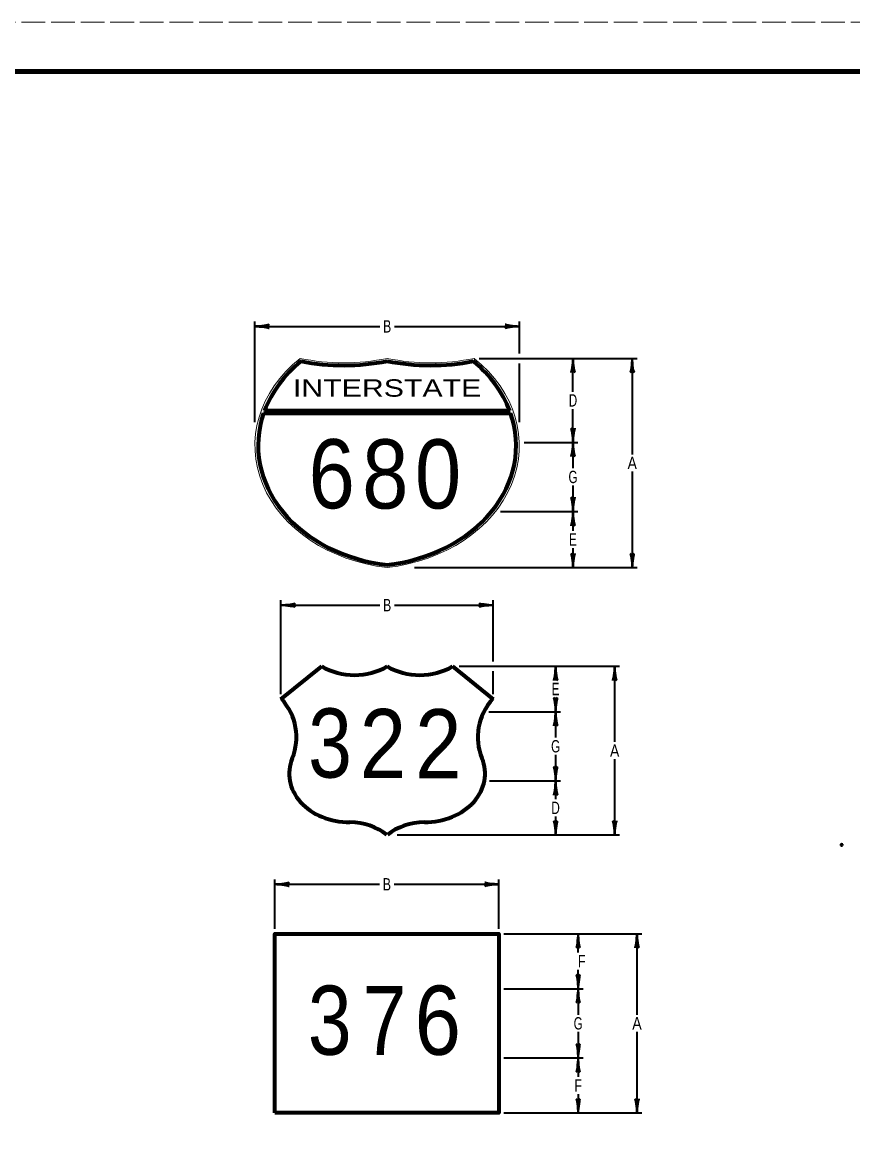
# Model space of a CAD drawing. Extents: x -55 to 625, y -354 to 86.
# Drawn here: x 113.3 to 281.5, y -138.9 to 86.4 of the extents above; entities that cross this region are included whole.
import ezdxf
from ezdxf.enums import TextEntityAlignment as Align

# ---------------------------------------------------------------- set-up
doc = ezdxf.new("R2010")
doc.units = 0
doc.header["$LTSCALE"] = 0.8
doc.header["$PDMODE"] = 32
doc.header["$PDSIZE"] = 0.4
doc.linetypes.add('LONG_DASHED', pattern=[7.5, 6, -1.5])
doc.layers.add('1', color=7, linetype='Continuous', lineweight=40)
doc.layers.add('61', color=7, linetype='Continuous', lineweight=35)

msp = doc.modelspace()

# ---------------------------------------------------------------- linework, layer by layer
at = {"layer": '1', "lineweight": 35}
for p, q in [((160.4495, 5.3879), (160.4495, 25.8174)), ((160.4495, 24.8174), (185.7309, 24.8174)), ((188.7309, 24.8174), (214.0122, 24.8174)), ((214.0122, 19.327), (214.0122, 25.8174)), ((205.8775, 18.327), (237.8775, 18.327)), ((224.8775, 11.577), (224.8775, 18.327)), ((236.8775, 18.327), (236.8775, -1.0995)), ((214.0122, 5.3879), (214.0122, 17.327)), ((224.8775, 1.327), (224.8775, 8.077)), ((215.0039, 1.327), (225.8775, 1.327)), ((224.8775, 1.327), (224.8775, -3.923)), ((236.8775, -4.5995), (236.8775, -24.026)), ((210.173, -12.673), (225.8775, -12.673)), ((224.8775, -20.0995), (224.8775, -24.026)), ((192.7598, -24.026), (237.8775, -24.026)), ((165.7252, -49.6412), (165.7252, -30.6412)), ((208.7364, -43.024), (208.7364, -30.6412)), ((165.7252, -31.6407), (185.7308, -31.6407)), ((188.7308, -31.6407), (208.7364, -31.6407)), ((201.829, -44.024), (234.3187, -44.024)), ((208.7364, -49.6412), (208.7364, -45.024)), ((221.3584, -46.8657), (221.3584, -44.024)), ((233.3187, -44.024), (233.3187, -59.3457)), ((221.3584, -53.2072), (221.3584, -50.3657)), ((207.844, -53.2072), (222.3584, -53.2072)), ((221.3584, -53.2072), (221.3584, -58.4572)), ((233.3187, -62.8457), (233.3187, -78.1672)), ((207.9489, -67.2073), (222.3584, -67.2073)), ((221.3584, -74.4372), (221.3584, -78.1672)), ((189.2805, -78.1672), (234.3187, -78.1672)), ((164.4938, -97.1672), (164.4938, -87.1672)), ((209.868, -97.1661), (209.868, -87.1661)), ((164.4938, -88.1661), (185.6809, -88.1661)), ((188.6809, -88.1661), (209.868, -88.1661)), ((210.868, -98.1661), (238.8357, -98.1661)), ((225.9311, -101.9911), (225.9311, -98.1661)), ((237.8357, -98.1661), (237.8357, -114.5661)), ((225.9311, -109.3161), (225.9311, -105.4911)), ((210.868, -109.3161), (226.9311, -109.3161)), ((225.9311, -109.3161), (225.9311, -114.5661)), ((237.8357, -118.0661), (237.8357, -134.4661)), ((210.868, -123.3161), (226.9311, -123.3161)), ((225.9311, -130.6411), (225.9311, -134.4661)), ((210.868, -134.4661), (238.8357, -134.4661))]:
    msp.add_line(p, q, dxfattribs=at)
at = {"layer": '1', "lineweight": 70}
for p, q in [((162.2153, 7.2148), (212.2463, 7.2148)), ((212.0572, 7.7394), (162.4044, 7.7394)), ((165.7252, -50.6412), (173.9955, -44.0252)), ((200.4658, -44.0252), (208.7364, -50.6412))]:
    msp.add_line(p, q, dxfattribs=at)
at = {"layer": '1', "lineweight": 35}
for points in [[(224.8775, -7.423), (224.8775, -12.673), (224.8775, -16.5995)], [(221.3584, -61.9572), (221.3584, -67.2073), (221.3584, -70.9372)], [(225.9311, -118.0661), (225.9311, -123.3161), (225.9311, -127.1411)]]:
    msp.add_lwpolyline(points, dxfattribs=at)
at = {"layer": '1', "lineweight": 70}
msp.add_lwpolyline([(164.4938, -134.4661), (164.4938, -98.1672), (209.868, -98.1672), (209.868, -134.4661)], close=True, dxfattribs=at)
at = {"layer": '1'}
for centre, major_axis, ratio, start_param, end_param in [((161.57, 24.6058), (-1.7565, 0.1757), 0.07063, 3.14071475, 5.41810995), ((161.57, 24.6058), (-1.7565, 0.1757), 0.07063, 3.14071475, 5.41810995), ((161.5407, 25.0937), (-1.7857, -0.1562), 0.122415, 0.89635335, 3.14159265), ((161.5407, 25.0937), (-1.7857, -0.1562), 0.122415, 0.89635335, 3.14159265), ((212.9211, 24.5411), (1.7857, 0.1562), 0.122415, 0.89635335, 3.14159265), ((212.9211, 24.5411), (1.7857, 0.1562), 0.122415, 0.89635335, 3.14159265), ((212.8917, 25.029), (1.7565, -0.1757), 0.07063, 3.14071475, 5.41810995), ((212.8917, 25.029), (1.7565, -0.1757), 0.07063, 3.14071475, 5.41810995), ((224.6659, 17.2065), (0.1757, 1.7565), 0.07063, 3.14071475, 5.41810995), ((225.1538, 17.2358), (-0.1562, 1.7857), 0.122415, 0.89635335, 3.14159265), ((236.6659, 17.2065), (0.1757, 1.7565), 0.07063, 3.14071475, 5.41810995), ((236.6659, 17.2065), (0.1757, 1.7565), 0.07063, 3.14071475, 5.41810995), ((237.1538, 17.2358), (-0.1562, 1.7857), 0.122415, 0.89635335, 3.14159265), ((237.1538, 17.2358), (-0.1562, 1.7857), 0.122415, 0.89635335, 3.14159265), ((224.6012, 2.4182), (0.1562, -1.7857), 0.122415, 0.89635335, 3.14159265), ((224.6012, 2.4182), (0.1562, -1.7857), 0.122415, 0.89635335, 3.14159265), ((225.0891, 2.4475), (-0.1757, -1.7565), 0.07063, 3.14071475, 5.41810995), ((225.0891, 2.4475), (-0.1757, -1.7565), 0.07063, 3.14071475, 5.41810995), ((224.6659, 0.2065), (0.1757, 1.7565), 0.07063, 3.14071475, 5.41810995), ((224.6659, 0.2065), (0.1757, 1.7565), 0.07063, 3.14071475, 5.41810995), ((225.1538, 0.2358), (-0.1562, 1.7857), 0.122415, 0.89635335, 3.14159265), ((225.1538, 0.2358), (-0.1562, 1.7857), 0.122415, 0.89635335, 3.14159265), ((224.6012, -11.5818), (0.1562, -1.7857), 0.122415, 0.89635335, 3.14159265), ((224.6012, -11.5818), (0.1562, -1.7857), 0.122415, 0.89635335, 3.14159265), ((225.0891, -11.5525), (-0.1757, -1.7565), 0.07063, 3.14071475, 5.41810995), ((225.0891, -11.5525), (-0.1757, -1.7565), 0.07063, 3.14071475, 5.41810995), ((224.6659, -13.7935), (0.1757, 1.7565), 0.07063, 3.14071475, 5.41810995), ((224.6659, -13.7935), (0.1757, 1.7565), 0.07063, 3.14071475, 5.41810995), ((225.1538, -13.7642), (-0.1562, 1.7857), 0.122415, 0.89635335, 3.14159265), ((225.1538, -13.7642), (-0.1562, 1.7857), 0.122415, 0.89635335, 3.14159265), ((224.6012, -22.9348), (0.1562, -1.7857), 0.122415, 0.89635335, 3.14159265), ((224.6012, -22.9348), (0.1562, -1.7857), 0.122415, 0.89635335, 3.14159265), ((225.0891, -22.9055), (-0.1757, -1.7565), 0.07063, 3.14071475, 5.41810995), ((225.0891, -22.9055), (-0.1757, -1.7565), 0.07063, 3.14071475, 5.41810995), ((236.6012, -22.9348), (0.1562, -1.7857), 0.122415, 0.89635335, 3.14159265), ((236.6012, -22.9348), (0.1562, -1.7857), 0.122415, 0.89635335, 3.14159265), ((237.0891, -22.9055), (-0.1757, -1.7565), 0.07063, 3.14071475, 5.41810995), ((237.0891, -22.9055), (-0.1757, -1.7565), 0.07063, 3.14071475, 5.41810995), ((166.8164, -31.3644), (-1.7857, -0.1562), 0.122415, 0.89635335, 3.14159265), ((166.8164, -31.3644), (-1.7857, -0.1562), 0.122415, 0.89635335, 3.14159265), ((207.6159, -31.4291), (1.7565, -0.1757), 0.07063, 3.14071475, 5.41810995), ((207.6159, -31.4291), (1.7565, -0.1757), 0.07063, 3.14071475, 5.41810995), ((166.8457, -31.8523), (-1.7565, 0.1757), 0.07063, 3.14071475, 5.41810995), ((166.8457, -31.8523), (-1.7565, 0.1757), 0.07063, 3.14071475, 5.41810995), ((207.6452, -31.917), (1.7857, 0.1562), 0.122415, 0.89635335, 3.14159265), ((207.6452, -31.917), (1.7857, 0.1562), 0.122415, 0.89635335, 3.14159265), ((221.1468, -45.1445), (0.1757, 1.7565), 0.07063, 3.14071475, 5.41810995), ((221.1468, -45.1445), (0.1757, 1.7565), 0.07063, 3.14071475, 5.41810995), ((221.6347, -45.1152), (-0.1562, 1.7857), 0.122415, 0.89635335, 3.14159265), ((221.6347, -45.1152), (-0.1562, 1.7857), 0.122415, 0.89635335, 3.14159265), ((233.1071, -45.1445), (0.1757, 1.7565), 0.07063, 3.14071475, 5.41810995), ((233.1071, -45.1445), (0.1757, 1.7565), 0.07063, 3.14071475, 5.41810995), ((233.595, -45.1152), (-0.1562, 1.7857), 0.122415, 0.89635335, 3.14159265), ((233.595, -45.1152), (-0.1562, 1.7857), 0.122415, 0.89635335, 3.14159265), ((221.0821, -52.1161), (0.1562, -1.7857), 0.122415, 0.89635335, 3.14159265), ((221.0821, -52.1161), (0.1562, -1.7857), 0.122415, 0.89635335, 3.14159265), ((221.57, -52.0867), (-0.1757, -1.7565), 0.07063, 3.14071475, 5.41810995), ((221.57, -52.0867), (-0.1757, -1.7565), 0.07063, 3.14071475, 5.41810995), ((221.1468, -54.3278), (0.1757, 1.7565), 0.07063, 3.14071475, 5.41810995), ((221.1468, -54.3278), (0.1757, 1.7565), 0.07063, 3.14071475, 5.41810995), ((221.6347, -54.2984), (-0.1562, 1.7857), 0.122415, 0.89635335, 3.14159265), ((221.6347, -54.2984), (-0.1562, 1.7857), 0.122415, 0.89635335, 3.14159265), ((221.0821, -66.1161), (0.1562, -1.7857), 0.122415, 0.89635335, 3.14159265), ((221.0821, -66.1161), (0.1562, -1.7857), 0.122415, 0.89635335, 3.14159265), ((221.57, -66.0867), (-0.1757, -1.7565), 0.07063, 3.14071475, 5.41810995), ((221.57, -66.0867), (-0.1757, -1.7565), 0.07063, 3.14071475, 5.41810995), ((221.1468, -68.3278), (0.1757, 1.7565), 0.07063, 3.14071475, 5.41810995), ((221.1468, -68.3278), (0.1757, 1.7565), 0.07063, 3.14071475, 5.41810995), ((221.6347, -68.2984), (-0.1562, 1.7857), 0.122415, 0.89635335, 3.14159265), ((221.6347, -68.2984), (-0.1562, 1.7857), 0.122415, 0.89635335, 3.14159265), ((221.0821, -77.0761), (0.1562, -1.7857), 0.122415, 0.89635335, 3.14159265), ((221.57, -77.0467), (-0.1757, -1.7565), 0.07063, 3.14071475, 5.41810995), ((233.0424, -77.0761), (0.1562, -1.7857), 0.122415, 0.89635335, 3.14159265), ((233.0424, -77.0761), (0.1562, -1.7857), 0.122415, 0.89635335, 3.14159265), ((233.5303, -77.0467), (-0.1757, -1.7565), 0.07063, 3.14071475, 5.41810995), ((233.5303, -77.0467), (-0.1757, -1.7565), 0.07063, 3.14071475, 5.41810995), ((165.585, -87.8898), (-1.7857, -0.1562), 0.122415, 0.89635335, 3.14159265), ((165.585, -87.8898), (-1.7857, -0.1562), 0.122415, 0.89635335, 3.14159265), ((208.7475, -87.9545), (1.7565, -0.1757), 0.07063, 3.14071475, 5.41810995), ((208.7475, -87.9545), (1.7565, -0.1757), 0.07063, 3.14071475, 5.41810995), ((165.6143, -88.3777), (-1.7565, 0.1757), 0.07063, 3.14071475, 5.41810995), ((165.6143, -88.3777), (-1.7565, 0.1757), 0.07063, 3.14071475, 5.41810995), ((208.7768, -88.4424), (1.7857, 0.1562), 0.122415, 0.89635335, 3.14159265), ((208.7768, -88.4424), (1.7857, 0.1562), 0.122415, 0.89635335, 3.14159265), ((225.7195, -99.2866), (0.1757, 1.7565), 0.07063, 3.14071475, 5.41810995), ((225.7195, -99.2866), (0.1757, 1.7565), 0.07063, 3.14071475, 5.41810995), ((226.2074, -99.2573), (-0.1562, 1.7857), 0.122415, 0.89635335, 3.14159265), ((226.2074, -99.2573), (-0.1562, 1.7857), 0.122415, 0.89635335, 3.14159265), ((237.6241, -99.2866), (0.1757, 1.7565), 0.07063, 3.14071475, 5.41810995), ((237.6241, -99.2866), (0.1757, 1.7565), 0.07063, 3.14071475, 5.41810995), ((238.112, -99.2573), (-0.1562, 1.7857), 0.122415, 0.89635335, 3.14159265), ((238.112, -99.2573), (-0.1562, 1.7857), 0.122415, 0.89635335, 3.14159265), ((225.6548, -108.2249), (0.1562, -1.7857), 0.122415, 0.89635335, 3.14159265), ((225.6548, -108.2249), (0.1562, -1.7857), 0.122415, 0.89635335, 3.14159265), ((226.1427, -108.1956), (-0.1757, -1.7565), 0.07063, 3.14071475, 5.41810995), ((226.1427, -108.1956), (-0.1757, -1.7565), 0.07063, 3.14071475, 5.41810995), ((225.7195, -110.4366), (0.1757, 1.7565), 0.07063, 3.14071475, 5.41810995), ((225.7195, -110.4366), (0.1757, 1.7565), 0.07063, 3.14071475, 5.41810995), ((226.2074, -110.4073), (-0.1562, 1.7857), 0.122415, 0.89635335, 3.14159265), ((226.2074, -110.4073), (-0.1562, 1.7857), 0.122415, 0.89635335, 3.14159265), ((225.6548, -122.2249), (0.1562, -1.7857), 0.122415, 0.89635335, 3.14159265), ((225.6548, -122.2249), (0.1562, -1.7857), 0.122415, 0.89635335, 3.14159265), ((226.1427, -122.1956), (-0.1757, -1.7565), 0.07063, 3.14071475, 5.41810995), ((226.1427, -122.1956), (-0.1757, -1.7565), 0.07063, 3.14071475, 5.41810995), ((225.7195, -124.4366), (0.1757, 1.7565), 0.07063, 3.14071475, 5.41810995), ((225.7195, -124.4366), (0.1757, 1.7565), 0.07063, 3.14071475, 5.41810995), ((226.2074, -124.4073), (-0.1562, 1.7857), 0.122415, 0.89635335, 3.14159265), ((226.2074, -124.4073), (-0.1562, 1.7857), 0.122415, 0.89635335, 3.14159265), ((225.6548, -133.3749), (0.1562, -1.7857), 0.122415, 0.89635335, 3.14159265), ((225.6548, -133.3749), (0.1562, -1.7857), 0.122415, 0.89635335, 3.14159265), ((226.1427, -133.3456), (-0.1757, -1.7565), 0.07063, 3.14071475, 5.41810995), ((226.1427, -133.3456), (-0.1757, -1.7565), 0.07063, 3.14071475, 5.41810995), ((237.5594, -133.3749), (0.1562, -1.7857), 0.122415, 0.89635335, 3.14159265), ((237.5594, -133.3749), (0.1562, -1.7857), 0.122415, 0.89635335, 3.14159265), ((238.0473, -133.3456), (-0.1757, -1.7565), 0.07063, 3.14071475, 5.41810995), ((238.0473, -133.3456), (-0.1757, -1.7565), 0.07063, 3.14071475, 5.41810995)]:
    msp.add_ellipse(centre, major_axis=major_axis, ratio=ratio, start_param=start_param, end_param=end_param, dxfattribs=at)
at = {"layer": '1', "lineweight": 13}
for centre, major_axis, start_param, end_param in [((191.6425, 0.6804), (-31.1952, 0), 5.49778714, 7.71208457), ((178.4075, 46.1205), (35.8448, 0), 4.46367898, 4.96109898), ((182.8192, 0.6804), (-31.1952, 0), 1.71269339, 3.92699082), ((196.0542, 46.1205), (35.8448, 0), 4.46367898, 4.96109898)]:
    msp.add_ellipse(centre, major_axis=major_axis, ratio=0.8, start_param=start_param, end_param=end_param, dxfattribs=at)
at = {"layer": '1', "lineweight": 70}
for centre, major_axis, start_param, end_param in [((191.6425, 0.6804), (-30.54, 0), 5.50987117, 5.99009653), ((178.4075, 46.1205), (36.4999, 0), 4.47398568, 4.95654246), ((196.0542, 46.1205), (36.4999, 0), 4.4682355, 4.95079228), ((182.8192, 0.6804), (-30.54, 0), 3.43468143, 3.91490679), ((191.6425, 0.6804), (-30.54, 0), 6.01242986, 7.71208457), ((182.8192, 0.6804), (-30.54, 0), 1.71269339, 3.4123481), ((180.6134, -36.9647), (11.0307, 0), 4.06899071, 5.3557872), ((193.8483, -36.9647), (11.0307, 0), 4.06899076, 5.35578725), ((151.7228, -58.3618), (17.1512, 0), 5.96604022, 6.8866281), ((222.7389, -58.3618), (17.1512, 0), 2.53814986, 3.45873774), ((179.6695, -65.7682), (12.2891, 0), 2.81786937, 4.7123069), ((194.7922, -65.7682), (12.2891, 0), 4.71247106, 6.60690859), ((179.6684, -83.9162), (-10.3963, 0), 3.90478078, 4.71238898), ((194.7933, -83.9162), (-10.3963, 0), 4.71238898, 5.51999719)]:
    msp.add_ellipse(centre, major_axis=major_axis, ratio=0.8, start_param=start_param, end_param=end_param, dxfattribs=at)
at = {"layer": '1'}
msp.add_point((279.2965, -80.1888), dxfattribs=at)
at = {"layer": '61', "linetype": 'LONG_DASHED', "lineweight": 13}
msp.add_line((-54.8373, 86.3965), (625.1827, 86.3965), dxfattribs=at)
at = {"layer": '61', "lineweight": 158}
msp.add_lwpolyline([(614.2027, 76.3965), (-24.8373, 76.3965), (-24.8373, -343.6235)], dxfattribs=at)

# ---------------------------------------------------------------- texts
at = {"layer": '1'}
for s, height, width, p in [('B', 2.5, 0.75, (187.231, 23.5674)), ('INTERSTATE', 3.529, 1.3, (187.2305, 10.5674)), ('D', 2.5, 0.7, (224.8775, 8.577)), ('A', 2.5, 0.85, (236.8775, -4.0995)), ('G', 2.5, 0.7, (224.8775, -6.923)), ('E', 2.5, 0.7, (224.8775, -19.5995)), ('B', 2.5, 0.75, (187.2309, -32.8907)), ('E', 2.5, 0.7, (221.3584, -49.8657)), ('G', 2.5, 0.7, (221.3584, -61.4572)), ('A', 2.5, 0.85, (233.3186, -62.3457)), ('D', 2.5, 0.7, (221.3585, -73.9372)), ('B', 2.5, 0.75, (187.181, -89.4161)), ('F', 2.5, 0.75, (226.643, -104.9824)), ('G', 2.5, 0.7, (225.931, -117.5661)), ('A', 2.5, 0.85, (237.8356, -117.5661)), ('F', 2.5, 0.75, (225.931, -130.1411))]:
    msp.add_text(s, height=height, dxfattribs=dict(at, width=width)).set_placement(p, align=Align.CENTER)
for s, width, p in [('6', 0.9, (171.3231, -12.0273)), ('8', 0.9, (182.1777, -12.0701)), ('0', 0.9, (192.8614, -12.0701)), ('3', 0.85, (171.2387, -66.5537)), ('2', 0.9, (181.6952, -66.6691)), ('2', 0.9, (192.9207, -66.7075)), ('3', 0.85, (171.1813, -122.6827)), ('7', 0.85, (182.2871, -122.7359)), ('6', 0.9, (192.8083, -122.6827))]:
    msp.add_text(s, height=14, dxfattribs=dict(at, width=width)).set_placement(p)

doc.saveas('drawing.dxf')
